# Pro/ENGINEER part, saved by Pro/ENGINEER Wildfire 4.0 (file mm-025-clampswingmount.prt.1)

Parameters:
  METRIC = "NO"

Other parameters: PITCH, DRILL_DIAMETER, THREAD_DIAMETER, THREADS_PER_INCH, CBORE_DIAMETER, CBORE_DEPTH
